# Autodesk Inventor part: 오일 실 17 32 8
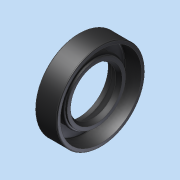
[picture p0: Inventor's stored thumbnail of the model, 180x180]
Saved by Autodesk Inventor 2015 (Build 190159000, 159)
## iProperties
Created: 2026-02
Part Number: 오일 실 17 32 8
Material: 일반
Document SubType Name: Modeling
Designer: Administrator
Density: 1 g/cm^3
Appearance: 기본값
Author: Administrator
Author: jhkim
Description: 오일-실
Creation Date: 2026-01-30
Sending System: Autodesk Inventor 2026
Preprocessor: ST-DEVELOPER v20.1
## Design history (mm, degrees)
node "오일 실 17 32 81"
body "Solid1"
node "기준1"
